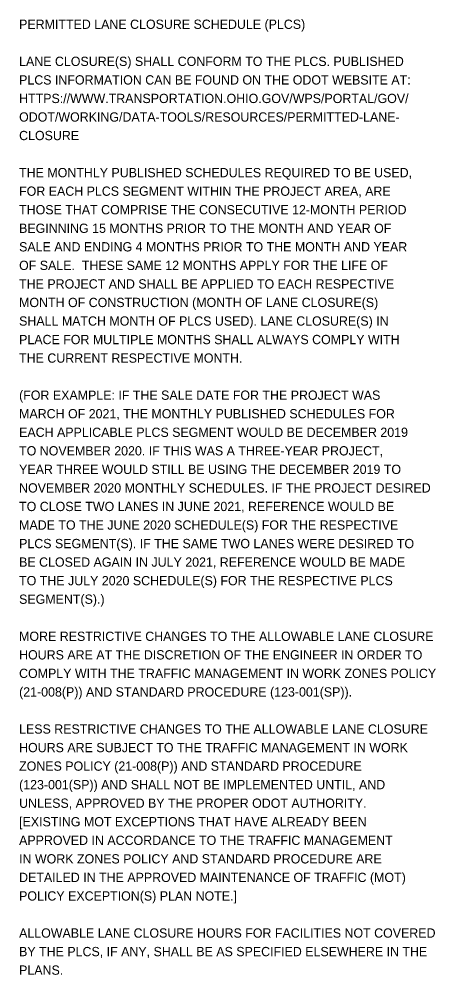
# Model space of a CAD drawing. Extents: x 0 to 257, y -39 to 22.
# Drawn here: x 112.19 to 118.48, y -39.27 to -24.84 of the extents above; entities that cross this region are included whole.
import ezdxf

# ---------------------------------------------------------------- set-up
doc = ezdxf.new("R2010")
doc.units = 0
doc.layers.add('SH_Text', color=7, linetype='Continuous')

msp = doc.modelspace()

# ---------------------------------------------------------------- texts
at = {"layer": 'SH_Text'}
for s, p in [('PERMITTED LANE CLOSURE SCHEDULE (PLCS)', (112.191, -24.99)), ('LANE CLOSURE(S) SHALL CONFORM TO THE PLCS. PUBLISHED', (112.191, -25.55)), ('PLCS INFORMATION CAN BE FOUND ON THE ODOT WEBSITE AT:', (112.191, -25.83)), ('HTTPS://WWW.TRANSPORTATION.OHIO.GOV/WPS/PORTAL/GOV/', (112.191, -26.11)), ('ODOT/WORKING/DATA-TOOLS/RESOURCES/PERMITTED-LANE-', (112.191, -26.39)), ('CLOSURE', (112.191, -26.67)), ('THE MONTHLY PUBLISHED SCHEDULES REQUIRED TO BE USED,', (112.191, -27.23)), ('FOR EACH PLCS SEGMENT WITHIN THE PROJECT AREA, ARE', (112.191, -27.51)), ('THOSE THAT COMPRISE THE CONSECUTIVE 12-MONTH PERIOD', (112.191, -27.79)), ('BEGINNING 15 MONTHS PRIOR TO THE MONTH AND YEAR OF', (112.191, -28.07)), ('SALE AND ENDING 4 MONTHS PRIOR TO THE MONTH AND YEAR', (112.191, -28.35)), ('OF SALE.  THESE SAME 12 MONTHS APPLY FOR THE LIFE OF', (112.191, -28.63)), ('THE PROJECT AND SHALL BE APPLIED TO EACH RESPECTIVE', (112.191, -28.91)), ('MONTH OF CONSTRUCTION (MONTH OF LANE CLOSURE(S)', (112.191, -29.19)), ('SHALL MATCH MONTH OF PLCS USED). LANE CLOSURE(S) IN', (112.191, -29.47)), ('PLACE FOR MULTIPLE MONTHS SHALL ALWAYS COMPLY WITH', (112.191, -29.75)), ('THE CURRENT RESPECTIVE MONTH.', (112.191, -30.03)), ('(FOR EXAMPLE: IF THE SALE DATE FOR THE PROJECT WAS', (112.191, -30.59)), ('MARCH OF 2021, THE MONTHLY PUBLISHED SCHEDULES FOR', (112.191, -30.87)), ('EACH APPLICABLE PLCS SEGMENT WOULD BE DECEMBER 2019', (112.191, -31.15)), ('TO NOVEMBER 2020. IF THIS WAS A THREE-YEAR PROJECT,', (112.191, -31.43)), ('YEAR THREE WOULD STILL BE USING THE DECEMBER 2019 TO', (112.191, -31.71)), ('NOVEMBER 2020 MONTHLY SCHEDULES. IF THE PROJECT DESIRED', (112.191, -31.99)), ('TO CLOSE TWO LANES IN JUNE 2021, REFERENCE WOULD BE', (112.191, -32.27)), ('MADE TO THE JUNE 2020 SCHEDULE(S) FOR THE RESPECTIVE', (112.191, -32.55)), ('PLCS SEGMENT(S). IF THE SAME TWO LANES WERE DESIRED TO', (112.191, -32.83)), ('BE CLOSED AGAIN IN JULY 2021, REFERENCE WOULD BE MADE', (112.191, -33.11)), ('TO THE JULY 2020 SCHEDULE(S) FOR THE RESPECTIVE PLCS', (112.191, -33.39)), ('SEGMENT(S).)', (112.191, -33.67)), ('MORE RESTRICTIVE CHANGES TO THE ALLOWABLE LANE CLOSURE', (112.191, -34.23)), ('HOURS ARE AT THE DISCRETION OF THE ENGINEER IN ORDER TO', (112.191, -34.51)), ('COMPLY WITH THE TRAFFIC MANAGEMENT IN WORK ZONES POLICY', (112.191, -34.79)), ('(21-008(P)) AND STANDARD PROCEDURE (123-001(SP)).', (112.191, -35.07)), ('LESS RESTRICTIVE CHANGES TO THE ALLOWABLE LANE CLOSURE', (112.191, -35.63)), ('HOURS ARE SUBJECT TO THE TRAFFIC MANAGEMENT IN WORK', (112.191, -35.91)), ('ZONES POLICY (21-008(P)) AND STANDARD PROCEDURE', (112.191, -36.19)), ('(123-001(SP)) AND SHALL NOT BE IMPLEMENTED UNTIL, AND', (112.191, -36.47)), ('UNLESS, APPROVED BY THE PROPER ODOT AUTHORITY.', (112.191, -36.75)), ('[EXISTING MOT EXCEPTIONS THAT HAVE ALREADY BEEN', (112.191, -37.03)), ('APPROVED IN ACCORDANCE TO THE TRAFFIC MANAGEMENT', (112.191, -37.31)), ('IN WORK ZONES POLICY AND STANDARD PROCEDURE ARE', (112.191, -37.59)), ('DETAILED IN THE APPROVED MAINTENANCE OF TRAFFIC (MOT)', (112.191, -37.87)), ('POLICY EXCEPTION(S) PLAN NOTE.]', (112.191, -38.15)), ('ALLOWABLE LANE CLOSURE HOURS FOR FACILITIES NOT COVERED', (112.191, -38.71)), ('BY THE PLCS, IF ANY, SHALL BE AS SPECIFIED ELSEWHERE IN THE', (112.191, -38.99)), ('PLANS.', (112.191, -39.27))]:
    msp.add_text(s, height=0.14, dxfattribs=at).set_placement(p)

doc.saveas('drawing.dxf')
